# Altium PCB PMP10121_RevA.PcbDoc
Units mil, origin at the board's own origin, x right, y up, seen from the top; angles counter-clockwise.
Board outline 5650 x 1182.11 mil, 2 copper layers (Top Layer, Bottom Layer), stack 62 mil thick; 55 components, 32 nets, 129 pads, 74 vias.
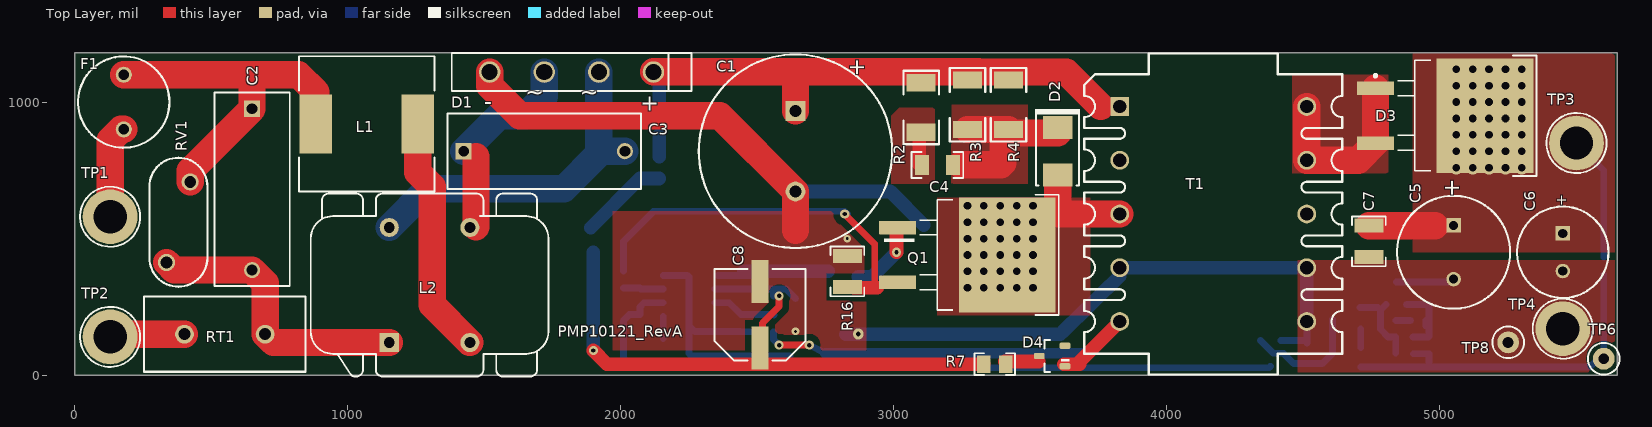
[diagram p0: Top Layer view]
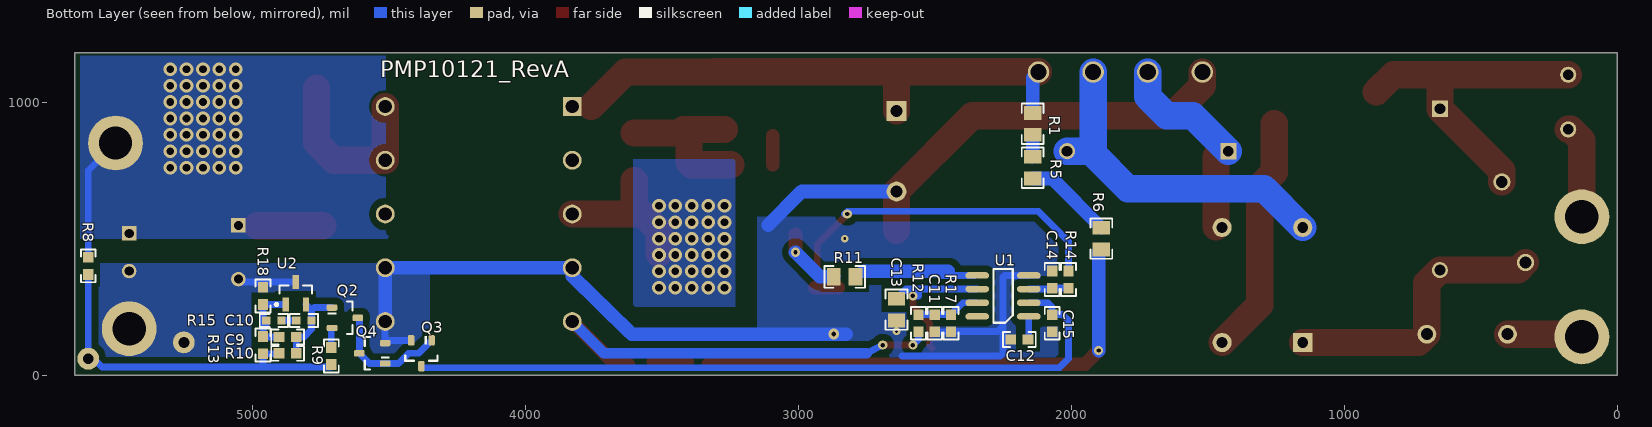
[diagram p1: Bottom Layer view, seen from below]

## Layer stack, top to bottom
Top Solder: solder mask 0.4, Solder Resist, Dk 3.5
Top Layer: signal copper 1.4
Dielectric1: core 59.2, FR-4, Dk 4.8
Bottom Layer: signal copper 1.4
Bottom Solder: solder mask 0.4, Solder Resist, Dk 3.5

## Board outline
0,0 5650,-1.01 5650,1180.1 0,1181.1

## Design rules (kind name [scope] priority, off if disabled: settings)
AcuteAngle [All] p1: minimum=4.50000000000000E+0001 checktracksonly=FALSE
AssemblyTestPointUsage [All] p1: valid=2
Clearance Clearance_Keepouts [((IsTrack Or IsArc) And Not InPoly) And IsFree and IsKeepOut vs ((IsTrack Or IsArc) And Not InPoly) And IsFree and IsKeepOut] p1: gap=0
Clearance Clearance_BoardEdge_MountingHoles [OnCopper and InComponentClass('Mounting Holes') vs IsKeepOut] p2: gap=40
Clearance Clearance_BoardEdge_Poly [OnCopper and InPoly vs IsKeepOut] p3: gap=25
Clearance Clearance_BoardEdge [OnCopper and Not InComponentClass('Logo') and not InComponentClass('FiducialMark') and not InRegion(1000,500,4000,800) and Not IsKeepout vs IsKeepOut] p4: gap=75
Clearance Clearance_Poly [InPolygon] p5: gap=25
Clearance [All] p6: gap=7.87
ComponentClearance ComponentClearance_MountingHoles_FiducialMarks [InComponentClass('Mounting Holes') vs InComponentClass('FiducialMark')] p1: gap=50 collisioncheckmode=3 verticalgap=10 showdistances=FALSE
ComponentClearance ComponentClearance_Shunt [InComponentClass('Header') vs InComponentClass('Shunt')] p2: gap=0 collisioncheckmode=3 verticalgap=0 showdistances=FALSE
ComponentClearance ComponentClearance_Logo [InComponentClass('Logo')] p3: gap=50 collisioncheckmode=3 verticalgap=10 showdistances=FALSE
ComponentClearance ComponentClearance_ScrewToNut [(HasFootprint('NY PMS 440 0025 PH')) vs (HasFootprint('Keystone_1902C'))] p4: gap=5 collisioncheckmode=3 verticalgap=10 showdistances=FALSE
ComponentClearance ComponentClearance_MountingHoles [InComponentClass('Mounting Holes')] p5: gap=250 collisioncheckmode=3 verticalgap=100000 showdistances=FALSE
ComponentClearance ComponentClearance_SmallPassives [HasFootprint('0201*') or HasFootprint('0402*') or HasFootprint('0508') or HasFootprint('0603*') or HasFootprint('0612') or HasFootprint('0805*') or HasFootprint('0815*') or HasFootprint('0830*') or HasFootprint('1206*') or HasFootprint('1210*') or HasFootprint('1808*') or HasFootprint('1812*') or HasFootprint('1825*') or HasFootprint('2010*') or HasFootprint('2220*') or HasFootprint('2225*') or HasFootprint('2512*') or HasFootprint('2728*') or HasFootprint('3518*') vs HasFootprint('0201*') or HasFootprint('0402*') or HasFootprint('0508') or HasFootprint('0603*') or HasFootprint('0612') or HasFootprint('0805*') or HasFootprint('0815*') or HasFootprint('0830*') or HasFootprint('1206*') or HasFootprint('1210*') or HasFootprint('1808*') or HasFootprint('1812*') or HasFootprint('1825*') or HasFootprint('2010*') or HasFootprint('2220*') or HasFootprint('2225*') or HasFootprint('2512*') or HasFootprint('2728*') or HasFootprint('3518*')] p6: gap=20 collisioncheckmode=3 verticalgap=10 showdistances=FALSE
ComponentClearance ComponentClearance_THtoSMT [IsThruComponent vs IsSMTComponent] p7: gap=10 collisioncheckmode=3 verticalgap=30 showdistances=FALSE
ComponentClearance ComponentClearance_THtoTH [IsThruComponent vs IsThruComponent] p8: gap=10 collisioncheckmode=3 verticalgap=30 showdistances=FALSE
ComponentClearance [All] p9: gap=40 collisioncheckmode=3 verticalgap=10 showdistances=FALSE
DiffPairsRouting [All] p1: maxlimit=100 minlimit=10 mostfreqgap=10 toplayer_minwidth=15 toplayer_maxwidth=15 toplayer_prefwidth=15 bottomlayer_minwidth=15 bottomlayer_maxwidth=15 bottomlayer_prefwidth=15 maxuncoupledlength=1000
FabricationTestPointUsage TestPointUsage [All] p1: valid=2 allowmultiple=FALSE
FabricationTestpoint Testpoint [All] p1: side=3 testpointundercomponent=TRUE minsize=40 maxsize=100 preferedsize=60 minholesize=0 maxholesize=40 preferedholesize=32 testpointgrid=1 allowsidetop=TRUE allowsidebottom=TRUE usegrid=TRUE gridtolerance=0.01
FanoutControl Fanout_LCC [IsLCC] p1: bgadir=Out bgaviamode=Centered fanoutstyle=Auto fanoutdirection=Alternating viagrid=1 // Fanout_LCC (Default Rule)
FanoutControl Fanout_BGA [IsBGA] p2: bgadir=Out bgaviamode=Centered fanoutstyle=Auto fanoutdirection=Alternating viagrid=1 // Fanout_BGA (Default Rule)
FanoutControl Fanout_Default [All] p4: bgadir=Out bgaviamode=Centered fanoutstyle=Auto fanoutdirection=Alternating viagrid=1 // Fanout_Default (Default Rule)
FanoutControl Fanout_Small [(CompPinCount < 5)] p5: bgadir=Out bgaviamode=Centered fanoutstyle=Auto fanoutdirection=OutThenIn viagrid=1 // Fanout_Small (Default Rule)
Height [All] p1: minheight=0 maxheight=1500 prefheight=500
HoleSize [All] p1: absolutevalues=TRUE maxlimit=251 minlimit=8 maxpercent=80.000 minpercent=20.000
MinimumAnnularRing MinimumAnnularRing_ThermalPadVias [IsVia and InAnyComponent] p1: minimumring=5.91
MinimumAnnularRing [All] p2: minimumring=9
MinimumSolderMaskSliver MinimumSolderMaskSliver_Logo [InComponentClass('Logo') vs InComponentClass('Logo')] p1: minsoldermaskwidth=0.7
MinimumSolderMaskSliver [All] p2: minsoldermaskwidth=3.94
PlaneConnect [All] p1: planeconnectstyle=Relief reliefexpansion=10 reliefentries=4 reliefconductorwidth=10 reliefairgap=10
PolygonConnect [All] p1: connectstyle=Direct reliefconductorwidth=10 reliefentries=4 polygonreliefangle="90 Angle" airgapwidth=10
RoutingVias ThermalPadVias [IsVia and InAnyComponent] p1: holewidth=7.87 width=19.68 viastyle="Through Hole" minholewidth=7.87 minwidth=19.68 maxholewidth=12.99 maxwidth=23.62
RoutingVias [All] p2: holewidth=16 width=34 viastyle="Through Hole" minholewidth=7.87 minwidth=26 maxholewidth=40 maxwidth=65
SilkToBoardRegionClearance [Not ((IsComment or IsDesignator) And (Hide <> 'False')) and not InRegion(1000,500,4000,800)] p1 off:
SilkToSilkClearance SilkToSilkClearance_Pb-FreeLogo [(HasFootprint('Pb-Free_Overlay_Medium') OR HasFootprint('Pb-Free_Overlay_Small')) vs (HasFootprint('Pb-Free_Overlay_Medium') OR HasFootprint('Pb-Free_Overlay_Small'))] p1: silktosilkclearance=0
SilkToSilkClearance [All] p2: silktosilkclearance=0
SilkToSolderMaskClearance "Silk to Solder Mask Opening" [All] p1: minsilkscreentomaskgap=0 clearancetoexposedcopper=FALSE
SolderMaskExpansion [All] p1: expansion=1.97
UnpouredPolygon [All] p1: allowunpoured=FALSE
Width [All] p1: maxlimit=100 minlimit=6 preferedwidth=10 checkconnectedcopper=TRUE
13 further rules are at their usual default settings.

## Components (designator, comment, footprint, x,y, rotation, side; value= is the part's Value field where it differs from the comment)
C1 "EEUED2W470" CAPPR7.5-18X31.5 2640,820 r270 top
C2 "B32922C3224K" B32922_12.5mm 650,680 r270 top
C3 "B32922C3224K" B32922_12.5mm 1720,820 r0 top
C4 "GRM31BR72J472KW01L" 1206 3160,770 r0 top
C5 "EKZN350ELL471MJ20S" KZN_1000x2000 5050,450 r270 top
C6 "EKZN350ELL221MH15D" KZN_800x1500 5450,450 r270 top
C7 "Used in BOM report" 1210 4740,490 r270 top
C8 "EEE-FC1V330P" SM_RADIAL_E 2510,221.5 r90 top
C9 "GRM188R71H103KA01D" 0603 4870,140 r180 bottom
C10 "Used in BOM report" 0603_HV 4810,200 r180 bottom
C11 "C0603C100J5GACTU" 0603 2500,190 r270 bottom
C12 "C1608X7R1H473K" 0603 2190,130 r0 bottom
C13 "GRM21BR71H104KA01L" 0805_HV 2640,240 r270 bottom
C14 "C0603C101J5GAC" 0603 2070,350 r90 bottom
C15 "C1608C0G1H102J" 0603 2070,190 r270 bottom
D1 "GBU8J-BP" GBU 1820,1110 r180 top
D2 "RS1MB-13-F" SMB 3600,820 r270 top
D3 "Used in BOM report" DDPAK#1 5010,950 r0 top
D4 "BAS21-7-F" SOT-23 3580,70 r180 top
F1 "37211600001" FUSE_372 180,1000 r270 top
L1 "MSS1210-334KE" IND_MSS1210 1070,920 r0 top
L2 "744823210" IND_WE-CMB_M 1300,330 r90 top
Q1 "STB11N65M5" DDPAK#2 3260,440 r0 top
Q2 "MMBT2907A" SOT-23 4660,210 r180 bottom
Q3 "MMBT3904" SOT-23 4380,80 r270 bottom
Q4 "MMBT3904" SOT-23 4560,80 r0 bottom
R1 "CRCW08052M00JNEA" 0805_HV 2141.46,920 r90 bottom
R2 "CRCW2010100RJNEF" 2010 3100,980 r90 top
R3 "CRCW2010100KJNEF" 2010 3270,990 r90 top
R4 "CRCW2010100KJNEF" 2010 3420,990 r90 top
R5 "CRCW08052M00JNEA" 0805_HV 2141.46,760 r90 bottom
R6 "CRCW08052M00JNEA" 0805_HV 1890,500 r90 bottom
R7 "CRCW080522R0JNEA" 0805_HV 3370,40 r0 top
R8 "CRCW060349R9FKEA" 0603 5600,400 r90 bottom
R9 "CRCW060320K0FKEA" 0603 4710,70 r270 bottom
R10 "CRCW060320K0FKEA" 0603 4870,80 r0 bottom
R11 "CRCW08050000Z0EA" 0805_HV 2830,360 r0 bottom
R12 "CRCW0603147KFKEA" 0603 2560,190 r270 bottom
R13 "CRCW060349K9FKEA" 0603 4960,110 r270 bottom
R14 "CRCW06031K43FKEA" 0603 2010,350 r90 bottom
R15 "Used in BOM report" 0603_HV 4920,200 r0 bottom
R16 "Used in BOM report" 1210 2830,380 r270 top
R17 "CRCW060334K8FKEA" 0603 2440,190 r90 bottom
R18 "CRCW06033K01FKEA" 0603 4960,290 r270 bottom
RT1 "B57237S109M" S237 550,150 r0 top
RV1 "S10K275E2" VAR_S10K275E2 380,560 r90 top
T1 "750315220" WURTH_750315220 4170,590 r0 top
TP1 "Suggest using a net name here" Keystone1503-2 130,580 r0 top
TP2 "Suggest using a net name here" Keystone1503-2 130,140 r0 top
TP3 "Suggest using a net name here" Keystone1503-2 5500,850 r0 top
TP4 "Suggest using a net name here" Keystone1503-2 5450,170 r0 top
TP6 "5000" Keystone5000 5600,60 r0 top
TP8 "5001" Keystone5001 5250,120 r0 top
U1 "UCC28600D" D0008A_N 2250,290 r0 bottom
U2 "LMV431AIMFX/NOPB" MF03A_N 4840,300 r90 bottom

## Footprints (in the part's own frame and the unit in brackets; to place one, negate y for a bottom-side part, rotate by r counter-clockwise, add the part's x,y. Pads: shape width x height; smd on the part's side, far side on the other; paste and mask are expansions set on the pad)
0603 [mm] "0603 from SM-752 data"
  rect 1x0.95 smd: 1(-0.8,0) 2(0.8,0)
  silkscreen extent -1.52,-0.69 1.52,0.69, body extent -0.87,-0.47 0.87,0.47, height 0.85
0603_HV [mil] "Ernesto recommended land pattern.  26 mil between pads."
  rect 30x30 smd: 1(-28,0) 2(28,0)
  silkscreen extent -52,-24 52,24, body extent -34,-19 34,19, height 33
0805_HV [mil] "0805 with 30mil clearance between pads"
  rect 50x63 smd: 1(-40,0) 2(40,0)
  silkscreen extent -74,-40 74,40, body extent -43,-29 43,29, height 43
1206 [mm] "1206 from SM-752 data"
  rect 1.3x1.85 smd: 1(-1.45,0) 2(1.45,0)
  silkscreen extent -2.4,-1.21 2.4,1.21, body extent -1.7,-0.9 1.7,0.9, height 1.35
1210 [mm] "1210 from SM-752 data"
  rect 1.3x2.7 smd: 1(-1.45,0) 2(1.45,0)
  silkscreen extent -2.32,-1.57 2.32,1.57, body extent -1.7,-1.35 1.7,1.35, height 1.35
2010 [mm] "Chip Capacitor, Body 5.08x2.54mm, IPC Medium Density"
  rect 1.6x2.7 smd: 1(-2.3,0) 2(2.3,0)
  silkscreen extent -3.42,-1.65 3.42,1.65, body extent -2.73,-1.45 2.73,1.45, height 1.66
B32922_12.5mm [mm] "Epcos film capacitors, 15mm spacing"
  rect 1.5x1.5 hole 1: 1(-7.5,0)
  round 1.5 hole 1: 2(7.5,0)
  silkscreen extent -9,-3.5 9,3.5, body extent -9,-3.5 9,3.5, height 12.5
CAPPR7.5-18X31.5 [mm] "Capacitor, Electrolytic, Radial; Body 18 x 31.5 mm (Dia.xH typ); Pin Spacing 7.5 mm (typ)"
  rect 1.85x1.85 hole 1.1: 1(-3.75,0)
  round 1.85 hole 1.1: 2(3.75,0)
  silkscreen extent -9,-9 9,9, body extent -9.01,-9.01 9.01,9.01, height 33.5
D0008A_N [mm] "SOIC, 8-Leads, Body 4.9x3.9mm, Pitch 1.27mm, IPC Medium Density"
  oval 2.2x0.6 smd: 1(-2.4,1.905) 2(-2.4,0.635) 3(-2.4,-0.635) 4(-2.4,-1.905) 5(2.4,-1.905) 6(2.4,-0.635) 7(2.4,0.635) 8(2.4,1.905)
  silkscreen extent -0.9,-2.5 0.9,2.5, body extent -3,-2.45 3,2.45, height 1.63
DDPAK#1 [mil] "D2-PAK, 3-Pads, Body 9.7x10.4mm (max), TO-263AB, using Vishay Silionix recommended pad sizes"
  rect 135x49.49 smd: 1(-246.06,100) 3(-246.06,-100)
  rect 355x420 smd paste-181.1: 4(155.51,0)
  silkscreen extent -251,-220 344,220, body extent -295,-202 324,202, height 180
DDPAK#2 [mil] "D2-PAK, 3-Pads, Body 9.7x10.4mm (max), TO-263AB, using Vishay Silionix recommended pad sizes"
  rrect8% 135x49.49 smd: 1(-246.06,100) 3(-246.06,-100)
  rrect1% 355x420 smd paste-181.1: 4(155.51,0)
  silkscreen extent -295,-220 344,220, body extent -295,-202 324,202, height 180
FUSE_372 [mm] "LITTELFUSE"
  round 1.5 hole 1: 1(-2.54,0) 2(2.54,0)
  silkscreen extent -4.25,-4.25 4.25,4.25, body extent -4.26,-4.26 4.26,4.26, height 8
GBU [mm] "Comchip / Diodes Inc diode bridge"
  round 2 hole 1.5: 1(-7.62,0) 2(-2.54,0) 3(2.54,0) 4(7.62,0)
  silkscreen extent -11.15,-1.78 11.15,1.78, body extent -11.15,-1.76 11.15,1.8, height 21.55
IND_MSS1210 [mm] "Coilcraft MSS1210 series"
  rect 3x5.5 smd: 1(-4.75,0) 2(4.75,0)
  silkscreen extent -6.3,-6.3 6.3,6.3, body extent -6.15,-6.15 6.15,6.15, height 10.2
IND_WE-CMB_M [mil] "Wurth"
  rect 70x70 hole 40: 1(-210.63,147.64)
  round 70 hole 40: 2(210.63,147.64) 3(210.63,-147.64) 4(-210.63,-147.64)
  silkscreen extent -335,-435 335,435, body extent -335,-394 335,394, height 1044
Keystone1503-2 [mm] "Double Turret"
  round 5.1 hole 3.1: 1(0,0)
  silkscreen extent -2.79,-2.79 2.79,2.79, body extent -2.4,-2.4 2.38,2.4, height 9.22
Keystone5000 [mil] "For Keystone 500x miniature loop terminals"
  round 80 hole 40: 1(0,0)
  silkscreen extent -58,-58 58,58, body extent -49,-49 49,49, height 182
Keystone5001 [mil] "For Keystone 500x miniature loop terminals"
  round 80 hole 40: 1(0,0)
  silkscreen extent -58,-58 58,58, body extent -49,-49 49,49, height 182
KZN_800x1500 [mm] "TH, 2-Leads, Dia 8mm, Pin Spacing 3.5mm"
  rect 1.35x1.35 hole 0.85: 1(-1.75,0)
  round 1.35 hole 0.85: 2(1.75,0)
  silkscreen extent -4.25,-4.25 4.25,4.25, body extent -4.22,-4.24 4.3,4.24, height 16.5
KZN_1000x2000 [mm] "TH, 2-Leads, Dia 10mm, Pin Spacing 5mm"
  rect 1.35x1.35 hole 0.85: 1(-2.5,0)
  round 1.35 hole 0.85: 2(2.5,0)
  silkscreen extent -5.25,-5.25 5.25,5.25, body extent -5.26,-5.26 5.26,5.26, height 21.5
MF03A_N [mm] "SOT23, 3-Leads, Body 2.9x1.3mm, Pitch 0.95mm, Lead Span 2.4mm, IPC Medium Density"
  rect 1.3x0.6 smd: 1(-1.05,0.95) 2(-1.05,-0.95) 3(1.05,0)
  silkscreen extent -1.17,-1.5 0.7,1.93, body extent -0.7,-1.5 0.7,1.5, height 1.12
S237 [mm] "EPCOS"
  round 1.75 hole 1.1: 1(-3.75,0) 2(3.75,0)
  silkscreen extent -7.5,-3.5 7.5,3.5, body extent -7.47,-3.5 7.47,3.5, height 21.99
SM_RADIAL_E [mm] "8 x 6.2mm:  Panasonic E"
  rect 4x1.6 smd: 1(-3.1,0) 2(3.1,0)
  silkscreen extent -4.25,-4.25 4.25,4.25, body extent -4.26,-4.26 4.26,4.26, height 6.5
SMB [mil] "Molded Diode, 2-Leads, Body 5.4x3.6mm, IPC Medium Density, based on OnSemi component dimensions"
  rect 85x107.99 smd: 1(-87.01,0) 2(87.01,0)
  silkscreen extent -155,-82 125,82, body extent -106,-71 106,71, height 91
SOT-23 [mm] "SOT23, 3-Leads, Body 2.9x1.3mm, Pitch 0.95mm, Lead Span 2.5mm, IPC Medium Density"
  rrect50% 1x0.6 smd: 1(-1.2,0.95) 2(-1.2,-0.95) 3(1.2,0)
  silkscreen extent -1.63,-1.5 0.7,1.5, body extent -1.16,-1.45 1.21,1.45, height 1
VAR_S10K275E2 [mm] "EPCOS"
  round 1.6 hole 1.1: 1(-3.75,1.1) 2(3.75,-1.1)
  silkscreen extent -6,-2.7 6,2.7, body extent -5.98,-2.7 5.98,2.7, height 14.99
WURTH_750315220 [mm] "TH, 10-Leads, Body 24x29.84mm, Pitch 5mm"
  rect 1.75x1.75 hole 1.25: 1(-8.7,10)
  round 1.75 hole 1.25: 2(-8.7,5) 3(-8.7,0) 4(-8.7,-5) 5(-8.7,-10) 6(8.7,-10) 7(8.7,-5) 8(8.7,0) 9(8.7,5) 10(8.7,10)
  silkscreen extent -12,-14.92 12,14.92, body extent -12,-14.92 12,14.92, height 33

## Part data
C1: "CAP, AL, 47 µF, 450 V, +/- 20%, 0.609529 ohm, TH"
C2 C3: "CAP, Film, 0.22 µF, 630 V, +/- 10%, TH"
C4: "CAP, CERM, 4700 pF, 630 V, +/- 10%, X7R, 1206"
C5: "CAP, AL, 470 µF, 35 V, +/- 20%, 0.028 ohm, TH"
C6: "CAP, AL, 220 µF, 35 V, +/- 20%, 0.059 ohm, TH"
C7 C10: library part Capacitor, "CAP, CERM, xxxF, xxV, [TempCo], xx%, [PackageReference]"
C8: "CAP, AL, 33 µF, 35 V, +/- 20%, 0.4 ohm, SMD"
C9: "CAP, CERM, 0.01 µF, 50 V, +/- 10%, X7R, 0603"
C11: "CAP, CERM, 10 pF, 50 V, +/- 5%, C0G/NP0, 0603"
C12: "CAP, CERM, 0.047 µF, 50 V, +/- 10%, X7R, 0603"
C13: "CAP, CERM, 0.1 µF, 50 V, +/- 10%, X7R, 0805"
C14: "CAP, CERM, 100 pF, 50 V, +/- 5%, C0G/NP0, 0603"
C15: "CAP, CERM, 1000 pF, 50 V, +/- 5%, C0G/NP0, 0603"
D1: "Diode, Switching-Bridge, 420 V, 8 A, TH"
D2: "Diode, P-N, 1000 V, 1 A, SMB"
D3: library part Diode_Schottky_A3C4, "Diode, Schottky, xxV, xxA, [PackageReference]"
D4: "Diode, Switching, 200 V, 0.2 A, SOT-23"
F1: "Fuse, 1.6 A, 250 V, TH"
L1: "Inductor, Shielded, Ferrite, 330 µH, 1.7 A, 0.317 ohm, SMD"
L2: "Coupled inductor, 10 mH, 2 A, 0.125 ohm, +/- 30%, TH"
Q1: "MOSFET, N-CH, 710 V, 9 A, DDPAK"
Q2: library part "MMBT2907A, Fairchild Semiconductor", "Transistor, PNP, 60 V, 0.8 A, SOT-23"
Q3 Q4: library part "MMBT3904, Fairchild Semiconductor", "Transistor, NPN, 40 V, 0.2 A, SOT-23"
R1 R5 R6: "RES, 2.0 M, 5%, 0.125 W, 0805"
R2: "RES, 100, 5%, 0.75 W, 2010"
R3 R4: "RES, 100 k, 5%, 0.75 W, 2010"
R7: "RES, 22, 5%, 0.125 W, 0805"
R8: "RES, 49.9, 1%, 0.1 W, 0603"
R9 R10: "RES, 20.0 k, 1%, 0.1 W, 0603"
R11: "RES, 0, 5%, 0.125 W, 0805"
R12: "RES, 147 k, 1%, 0.1 W, 0603"
R13: "RES, 49.9 k, 1%, 0.1 W, 0603"
R14: "RES, 1.43 k, 1%, 0.1 W, 0603"
R15 R16: library part Resistor, "RES, xxx ohm, x%, xW, [PackageReference]"
R17: "RES, 34.8 k, 1%, 0.1 W, 0603"
R18: "RES, 3.01 k, 1%, 0.1 W, 0603"
RT1: "Thermistor NTC, 1 ohm, 20%, 15x7mm"
RV1: "Varistor 275V RMS 10MM Radial, TH"
T1: "Transformer, 400 uH, TH"
TP1 TP2 TP3 TP4: library part 1503-2, "Terminal, Turret, TH, Double"
TP6: "Test Point, Miniature, Red, TH"
TP8: "Test Point, Miniature, Black, TH"
U1: "Quasi-Resonant Flyback Green-Mode Controller with Current Control, 99 % Duty Cycle, -40 to +105 degC, 8-pin SOIC (D), Green (RoHS & no Sb/Br)"
U2: "Low-Voltage (1.24V) Adjustable Precision Shunt Regulators, 3-pin SOT-23, Pb-Free"

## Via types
v1: diameter 50, hole 28, Top Layer to Bottom Layer, 65 vias
v2: diameter 34, hole 16, Top Layer to Bottom Layer, 6 vias
v3: diameter 28, hole 10, Top Layer to Bottom Layer, 2 vias
v4: diameter 40, hole 18, Top Layer to Bottom Layer, 1 vias

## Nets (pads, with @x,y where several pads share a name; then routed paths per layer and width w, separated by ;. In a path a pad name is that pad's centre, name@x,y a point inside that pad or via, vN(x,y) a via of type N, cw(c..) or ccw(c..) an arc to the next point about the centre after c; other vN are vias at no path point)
GND: C1.2 C5.2 C6.2 C7.2 C8.2 C11.2 C12.2 C13.2 C14.2 C15.2 D1.4 Q3.2 Q4.2 R16.1 R17.1 R18.1 T1.4 T1.6 T1.7 TP4.1 TP8.1 U1.4 U2.3 | length 5356.7
  Top Layer w100: D1.4 1520,1060 1630,950 2362.36,950 C1.2 ; 2640,530 C1.2@2640,660
  Bottom Layer w25: U1.4 2245,365 2250,360 2250,180 ; C11.2 R17.1 2438.5,160 2270,160 2250,180 ; 2620,70 2260,70 2250,80 2250,180 ; Q3.2 Q4.2@4502.91,127.24 ; Q4.2 T1.6@4512.76,196.06 ; U2.3 5039.76,341.34 C5.2
  Bottom Layer w50: C1.2 2987.64,672.36 3110,550 ; 2825.04,150 3610,150 ; 3620,160 3827.48,362.52 T1.4 T1.7 T1.6
  other v3: 2640,160 2830,500
  other v4: 2870,150
NetC1_1: C1.1 D1.1 R1.2 R2.2 R3.2 R4.2 T1.1 | length 1982.4
  Top Layer w100: D1.1 2120,1110.55 3200.39,1110.55 ; C1.1@2640,967.09 2640,1100 ; 3200.94,1110 3200.39,1110.55 ; R3.2@3310.39,1110.55 3200.39,1110.55 ; R3.2@3310.94,1110 3631.18,1110 3757.48,983.7
  Bottom Layer w50: D1.1 2141.46,1088.54 R1.2
NetC2_1: C2.1 F1.1 L1.1 RV1.2 | length 1215.3
  Top Layer w100: F1.1 650,1100 ; RV1.2 423.31,748.58 C2.1 650,1100 ; 882.99,1037.01 820,1100 650,1100
NetC2_2: C2.2 L2.1 RT1.2 RV1.1 | length 1046.6
  Top Layer w100: RV1.1 364.33,384.72 C2.2 697.64,337.09 RT1.2 728.27,119.37 L2.1
NetC3_1: C3.1 D1.3 L2.3 | length 724.6
  Top Layer w100: L2.3@1470,543.54 1470,800
  Bottom Layer w100: C3.1 1554.72,950 1650,950 1720,1020 D1.3
NetC3_2: C3.2 D1.2 L2.2 | length 1264.5
  Bottom Layer w100: L2.2 1293.94,682.2 1792.2,682.2 1920,810 D1.2 ; 1930,820 C3.2
NetC4_1: C4.1 R2.1 | length 106.5
  Top Layer w50: C4.1@3093.07,770 R2.1@3093.07,876.54
NetC4_2: C4.2 D2.1 R3.1 R4.1 | length 594.2
  Top Layer w100: 3247.09,770 3392.99,770 ; R3.1 R4.1 3400,879.45 3400,777.01 ; R4.1@3432.44,887.01 D2.1@3600,887.01
NetC5_1: C5.1 C6.1 C7.1 D3.4 R8.2 TP3.1 | length 701.7
  Top Layer w100: C7.1 4981.81,547.09
  Bottom Layer w25: TP3.1 5600,750 R8.2
  other v1: 5060,760 5120,760 5180,760 5240,760 5300,760 5060,820 5120,820 5180,820 5240,820 5300,820 5060,880 5120,880 5180,880 5240,880 5300,880 5060,940 5120,940 5180,940 5240,940 5300,940 5060,1000 5120,1000 5180,1000 5240,1000 5300,1000 5060,1060 5120,1060 5180,1060 5240,1060 5300,1060 5060,1120 5120,1120 5180,1120 5240,1120 5300,1120
NetC9_1: C9.1 R13.1 R15.2 R18.2 U2.1 | length 291.4
  Bottom Layer w25: U2.1 R18.2@4959.84,258.66 ; C9.1 R13.1@4958.5,140 ; R15.2 4948,181.98 4960,169.98 ; R13.1 4960,169.98 ; R18.2 4960,169.98
NetC9_2: C9.2 C10.2 Q2.1 R10.1 U2.2 | length 292.7
  Bottom Layer w25: Q2.1 4772.66,247.4 ; U2.2 4782,238.06 C10.2 4782,168.02 4810.02,140 C9.2 R10.1
NetC10_1: C10.1 R15.1 | length 54
  Bottom Layer w25: C10.1 R15.1
NetC11_1: C11.1 R12.1 R17.2 U1.7 | length 235.6
  Bottom Layer w25: U1.7 2396.5,265 R17.2 C11.1 R12.1 R12.1@2561.5,220
NetC12_1: C12.1 U1.1 | length 82
  Bottom Layer w25: C12.1@2155.51,132.99 U1.1
NetC14_1: C14.1 R14.1 U1.3 | length 147
  Bottom Layer w25: R14.1 C14.1 2073.5,315 U1.3
NetC15_1: C15.1 Q3.3 U1.2 | length 2711
  Bottom Layer w25: U1.2 2085.02,265 2070,249.98 C15.1 2031.5,221.5 2010,200 2010,60 2042.87,27.13 Q3.3@4374.37,27.13 ; Q3.3@4377.24,30 Q3.3
NetD2_2: D2.2 Q1.4 T1.3 | length 520.6
  Top Layer w100: Q1.4@3510,444.49 3510,530.47 3569.53,590 T1.3 ; 3600,620.47 D2.2@3600,712.99
  other v1: 3270,320 3330,320 3390,320 3450,320 3510,320 3270,380 3330,380 3390,380 3450,380 3510,380 3270,440 3330,440 3390,440 3450,440 3510,440 3270,500 3330,500 3390,500 3450,500 3510,500 3270,560 3330,560 3390,560 3450,560 3510,560 3270,620 3330,620 3390,620 3450,620 3510,620
NetD3_1: D3.1 D3.3 T1.9 T1.10 | length 674.4
  Top Layer w100: T1.10 T1.9 4700.79,786.85 D3.3 D3.1
NetD4_1: D4.1 R12.2 T1.5 | length 1619.3
  Top Layer w25: v2(2580,110) v2(2690,110)
  Top Layer w50: D4.1@3623.46,40 3680,40 ; 3683.78,52.6 T1.5
  Bottom Layer w25: 2559.98,130.02 v2(2580,110) ; 2560,130.04 R12.2 ; v2(2690,110) 2750,80
  Bottom Layer w40: 2750,80 3711.18,80 T1.5
NetD4_3: D4.3 R7.2 | length 122.8
  Top Layer w50: R7.2@3407.24,50 3530,50
NetF1_2: F1.2 TP1.1 | length 346.6
  Top Layer w100: TP1.1 130,860 170,900 F1.2
NetL1_2: L1.2 L2.4 | length 879.6
  Top Layer w100: L1.2 1257.01,742.99 1310,690 1310,257.01 L2.4
NetQ1_1: Q1.1 R11.2 | length 243.3
  Top Layer w50: v2(3010,450) Q1.1@3010,516.06
  Bottom Layer w50: R11.2 2920,360 v2(3010,450)
NetQ1_3: Q1.3 R14.2 R16.2 | length 1380.9
  Top Layer w25: v2(2820,590) 2930,480 2930,320
  Top Layer w50: R16.2@2852.91,320 2940,320
  Bottom Layer w25: R14.2 2010,490 2120,600 2820,600 v2@2830,590
NetQ2_2: Q2.2 R9.1 | length 68.3
  Bottom Layer w25: R9.1 Q2.2@4710,169.84
NetQ2_3: Q2.3 Q3.1 Q4.1 Q4.3 | length 439.7
  Bottom Layer w25: Q3.1 4389.84,80 4427.07,80 4464.47,42.6 Q4.1 4569.84,42.6 Q4.3 Q2.3@4607.24,204.49
NetR1_1: R1.1 R5.2 | length 80
  Bottom Layer w50: R5.2 R1.1
NetR5_1: R5.1 R6.2 | length 326
  Bottom Layer w50: R6.2 2070,720 R5.1
NetR8_1: R8.1 R9.2 R10.2 R13.2 TP6.1 | length 1304.7
  Bottom Layer w25: R9.2@4710,30 4960,30 ; R10.2@4902.99,78.5 R13.2 4960,30 ; R8.1 5600,80 5550,30 4960,30
NetR11_1: R11.1 U1.5 | length 430.5
  Bottom Layer w25: U1.5@2354.49,365 2475,365
  Bottom Layer w50: 2450,380 2760,380
NetRT1_1: RT1.1 TP2.1 | length 262.4
  Top Layer w100: TP2.1@140,150 RT1.1
VDD: C8.1 C13.1 R6.1 R7.1 U1.6 | length 2375.3
  Top Layer w25: C8.1 2518.7,108.15 2518.7,190 2580,251.3 v2(2580,290)
  Top Layer w50: v2(1900,90) 1950,40 R7.1
  Bottom Layer w25: U1.6 2560,315 ; v2@2570,290 2560,290 2560,315 ; C13.1 2605,315 2560,315
  Bottom Layer w50: v2(1900,90) R6.1@1900,450
pads on no net: D4.2 T1.2 T1.8 U1.8

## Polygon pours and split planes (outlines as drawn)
NetD3_1 on Top Layer "Top Layer-No Net 6" (solid, remove dead copper, pour order 36): 4460,1100 4810,1100 4810,733.46 4803.46,740 4460,740
NetD2_2 on Top Layer "Top Layer-No Net 5" (solid, remove dead copper, pour order 30): 3160,650 3720,650 3720,220 3160,220
GND on Top Layer "Top Layer-No Net 4" (solid, remove dead copper, pour order 16): 1970,600 2900,600 2900,10 1970,10
GND on Top Layer "Top Layer-No Net 3" (solid, remove dead copper, pour order 12): 4480,420 5640,420 5640,10 4480,10
NetC5_1 on Top Layer "Top Layer-No Net" (solid, remove dead copper, pour order 10): 4900,1180 4900,450 5640,450 5640,1170 5630,1180
NetC4_1 on Top Layer "Top Layer-No Net 2" (solid, remove dead copper, pour order 8): 3150,700 3150,980 3020,980 2990,950 2990,700
NetC4_2 on Top Layer "Top Layer-No Net 1" (solid, remove dead copper, pour order 6): 3212.93,990 3490,990 3490,700 3220,700 3210,690
NetC5_1 on Bottom Layer "Bottom Layer-No Net 3" (solid, remove dead copper, pour order 34): 5630,500 4490,500 4510,520 4510,1170 5630,1170
GND on Bottom Layer "Bottom Layer-No Net 2" (solid, remove dead copper, pour order 32): 4350,20 4350,410 5640,410 5650,420 5630,400 5630,20
NetD2_2 on Bottom Layer "Bottom Layer-No Net 1" (solid, remove dead copper, pour order 28): 3230,250 3604,250 3604,790 3230,790
GND on Bottom Layer "Bottom Layer-No Net" (solid, remove dead copper, pour order 18): 1810,580 3150,580 3150,10 1810,10

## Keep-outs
Keep-Out Layer:
  text ".Layer_Name" at 577,-858.49 h60

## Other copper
Top Layer:
  text ".Layer_Name" at 577,-858.49 h60
Bottom Layer:
  text ".Layer_Name" at 577,-858.49 h60

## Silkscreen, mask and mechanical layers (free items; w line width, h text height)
Top Overlay:
  text "PMP10121_RevA" at 1770,140 h40
  text ".Layer_Name" at 577,-858.49 h60
Bottom Overlay:
  text "PMP10121_RevA" at 4530,1090 h60
  text ".Layer_Name" at 577,-858.49 h60
Top Paste:
  text ".Layer_Name" at 577,-858.49 h60
Bottom Paste:
  text ".Layer_Name" at 577,-858.49 h60
Top Solder:
  text ".Layer_Name" at 577,-858.49 h60
  text ".Layer_Name" at 577,-858.49 h60
Bottom Solder:
  text ".Layer_Name" at 577,-858.49 h60
Drill Guide:
  text ".Layer_Name" at 577,-858.49 h60
M1 Board Outline:
  the board outline again, w10
  text ".Layer_Name" at 577,-858.49 h60
M2 Board Dimensions:
  rectangle: 125,-400 500,-275
  rectangle: 0,-275 125,-150
  lines w7: 0,-275 1000,-275 ; 125,-400 125,-150 ; 250,-400 250,-150 ; 500,-400 500,-150 ; 750,-400 750,-150 ; 0,-400 0,-150 1000,-150 1000,-400 0,-400
  text ".Layer_Name" at 577,-858.49 h60
M3 3D STEP Top:
  text ".Layer_Name" at 577,-858.49 h60
M4 3D STEP Bottom:
  text ".Layer_Name" at 577,-858.49 h60
M5 Assembly Top:
  lines w10: -292,-930.17 6308,-930.17 ; -292,-726.83 6310,-726.83 ; -292,-523.5 -292,-1133.5 3713,-1133.5 6310,-1133.5 6310,-523.5 -291.5,-523.5 -291.5,-1133.5 1284,-1133.5 ; 2173,-1133.5 2173,-523.5 ; 3440,-726.83 3440,-523.5 ; 4280,-726.83 4280,-523.5 ; 4902,-1140 4902,-937.17
  text "PCB VIEWED FROM TOP SIDE" at -228.5,-655.67 h60
  text "BOARD #:" at 2248,-655.67 h60
  text ".PRJ_Number" at 2793.5,-655.67 h60
  text "REV:" at 3638,-655.67 h60
  text ".PCB_Rev" at 3929.5,-655.67 h60
  text "SVN REV:" at 4476,-655.67 h60
  text ".VersionControl_RevNumber" at 4982,-655.67 h60
  text "PLOT NAME =" at -228.5,-1064.34 h60
  text ".plot_File_Name" at 577,-1064.34 h60
  text "GENERATED    :" at 2250,-1064.34 h60
  text ".Print_Date" at 3119.5,-1064.34 h60
  text ".Print_Time" at 3848.5,-1064.34 h60
  text "TEXAS INSTRUMENTS" at 5113,-1064.34 h60
M6 Assembly Bottom:
  lines w10: -292.5,-727.33 6309.5,-727.33 ; -290.5,-930.67 6309.5,-930.67 ; 1115.5,-1140.5 1115.5,-937.67 ; 1737.5,-727.33 1737.5,-524 ; 2577.5,-727.33 2577.5,-524 ; 3844.5,-1134 3844.5,-524 ; 4733.5,-1134 6309,-1134 6309,-524 -292.5,-524 -292.5,-1134 2304.5,-1134 6309.5,-1134 6309.5,-524
  text ".VersionControl_RevNumber" at 1035.5,-656.17 h60
  text "SVN REV:" at 1541.5,-656.17 h60
  text ".PCB_Rev" at 2088,-656.17 h60
  text "REV:" at 2379.5,-656.17 h60
  text ".PRJ_Number" at 3224,-656.17 h60
  text "BOARD #:" at 3769.5,-656.17 h60
  text "PCB VIEWED FROM BOTTOM SIDE" at 6246,-656.17 h60
  text "TEXAS INSTRUMENTS" at 904.5,-1064.84 h60
  text ".Print_Time" at 2169,-1064.84 h60
  text ".Print_Date" at 2898,-1064.84 h60
  text "GENERATED    :" at 3767.5,-1064.84 h60
  text ".plot_File_Name" at 5440.5,-1064.84 h60
  text "PLOT NAME =" at 6246,-1064.84 h60
M9 Title Sheet:
  drawing of 57 lines, arcs and shapes, not listed
  text "1" at 739.84,8036.5 h70
  text "2" at 3235.5,8036.5 h70
  text "3" at 5724.84,8036.5 h70
  text "4" at 8231.51,8036.5 h70
  text "5" at 10730.5,8036.5 h70
  text "6" at 13235.5,8036.5 h70
  text "A" at -416.5,6893.5 h70
  text "A" at 14383.5,6893.5 h70
  text "B" at -416.5,4513.5 h70
  text "B" at 14383.5,4513.5 h70
  text "C" at -416.5,2138.5 h70
  text "C" at 14383.5,2138.5 h70
  text "PROJECT TITLE:" at 11343.5,277.5 h45
  text ".PRJ_Title" at 11393.5,144.17 h70
  text "DESIGNED FOR:" at 11343.5,-23.5 h45
  text ".PRJ_Customer" at 11393.5,-163.5 h70
  text "D" at -416.5,-231.5 h70
  text "D" at 14383.5,-231.5 h70
  text "FILE NAME:" at 11343.5,-323.5 h45
  text ".PCB_File_Name_No_Path" at 11393.5,-443.5 h70
  text "Texas Instruments (TI) and/or its licensors do not warrant the accuracy or completeness of this specification" at 6374,-605.34 h45
  text "ENGINEER:" at 11343.5,-613.5 h45
  text "LAYOUT BY:" at 12848.5,-613.5 h45
  text "or any information contained therein. TI and/or its licensors do not warrant that this design will meet" at 6329.01,-718 h45
  text ".PRJ_Engineer" at 11393.5,-768.49 h70
  text ".PCB_Layout" at 12899,-768.49 h70
  text "the specifications, will be suitable for your application or fit for any particular purpose, or will operate in" at 6329.01,-830.67 h45
  text ".Layer_Name" at 577,-858.49 h60
  text "ALTIUM DESIGNER VERSION:" at 12848.5,-923.5 h45
  text "an implementation. TI and/or its licensors do not warrant that the design is production worthy. You should" at 6329.01,-943.33 h45
  text "completely validate and test your design implementation to confirm the system functionality for your application." at 6374,-1056 h45
  text ".print_Scale" at 11393.5,-1056.83 h70
  text ".Application_BuildNumber" at 12899,-1056.83 h70
  text "1" at 739.84,-1263.5 h70
  text "2" at 3235.5,-1263.5 h70
  text "3" at 5724.84,-1263.5 h70
  text "4" at 8231.51,-1263.5 h70
  text "5" at 10730.5,-1263.5 h70
  text "6" at 13235.5,-1263.5 h70
M10 Fab Notes:
  drawing of 185 lines, arcs and shapes, not listed
  text "DESIGN INFORMATION" at 12381.02,5910 h60
  text "MIN. TRACK WIDTH:" at 11736.46,5730 h60
  text "8" at 12832.7,5730 h60
  text "MIL" at 12987.46,5730 h60
  text "MIN. CLEARANCE:" at 11736.46,5598 h60
  text "0.2" at 12772.7,5598 h60
  text "mm" at 12987.46,5598 h60
  text "MIN. VIA PAD SIZE:" at 11736.46,5466 h60
  text "24" at 12802.71,5466 h60
  text "MIL" at 12987.46,5466 h60
  text "0.05mm (2MIL)" at 12431.46,5324.29 h60
  text "MINIMUM ANNULAR RING" at 11407.23,5320 h60
  text "EXTERNAL" at 13139.46,5320 h60
  text "PER" at 11607.23,5202 h60
  text "IPC-D-275 CLASS 2 LEVEL C" at 11827.23,5202 h60
  text "MIL, HOLES" at 13315.46,5089.71 h60
  text "+/-" at 12923,5089 h60
  text "+/-" at 13777,5089 h60
  text "REGISTRATION TOLERANCES:" at 11407.23,5084 h60
  text "METAL" at 12607,5084 h60
  text "5" at 13183.2,5084 h60
  text "3" at 14016.2,5084 h60
  text "MIL" at 14132.46,5084 h60
  text "MATERIAL:" at 11332.46,4874.54 h60
  text "FR-4 High Tg" at 12318.9,4734.21 h60
  text "FR-408" at 11753.46,4725.64 h60
  text "X" at 12165.46,4725.64 h60
  text "OTHER" at 13241.46,4725.64 h60
  text "62 MIL (1.6mm) +/-10%" at 12073.56,4562.92 h60
  text "THICKNESS:" at 11407.23,4558.64 h60
  text "X" at 11945.4,4558.64 h60
  text "OTHER" at 13358.46,4558.64 h60
  text "TOLERANCE:" at 11407.23,4400.64 h60
  text "X" at 12246.53,4400.64 h60
  text "ANSI IPC-6012 TYPE 3 CLASS 2" at 12433.48,4400.64 h60
  text "OTHER +/-" at 12433.46,4244.64 h60
  text "BOW & TWIST:" at 11407.23,4087.64 h60
  text "X" at 12246.53,4087.64 h60
  text "ANSI IPC-6012 TYPE 3 CLASS 2" at 12433.48,4087.64 h60
  text "OTHER +/-" at 12433.46,3929.13 h60
  text "DRILLING:" at 11332.46,3790.64 h60
  text "REFERENCE:" at 11407.23,3673.64 h60
  text "X" at 12055.46,3673.64 h60
  text "AS SHOWN" at 12242.46,3673.64 h60
  text "X" at 12956.46,3673.64 h60
  text "NC_DRILL FILES" at 13093.46,3673.64 h60
  text "PTH MIN COPPER THICKNESS:" at 11407.23,3515.64 h60
  text "X" at 12757.46,3515.64 h60
  text "1MIL" at 12894.46,3515.64 h60
  text "OTHER" at 13391.46,3515.64 h60
  text "BOARD FINISH:" at 11332.46,3356.64 h60
  text "SILKSCREEN:" at 11487.68,3238.64 h60
  text "X" at 12436.46,3238.64 h60
  text "TOP" at 12562.46,3238.64 h60
  text "X" at 12946.46,3238.64 h60
  text "BOTTOM" at 13073.46,3238.64 h60
  text "SILKSCREEN COLOR:" at 11487.68,3071.64 h60
  text "X" at 12435.42,3071.64 h60
  text "WHITE" at 12562.46,3071.64 h60
  text "OTHER" at 13073.46,3071.64 h60
  text "SOLDER RESIST COLOR:" at 11487.68,2901.64 h60
  text "X" at 12055.42,2742.44 h60
  text "GREEN" at 12182.46,2742.44 h60
  text "BLUE" at 12773.46,2742.44 h60
  text "OTHER" at 13311.46,2742.44 h60
  text "IMMERSION GOLD (ENIG)" at 12393.46,2553.92 h60
  text "ENEPIG" at 13731,2550.64 h60
  text "SURFACE FINISH:" at 11332.46,2549.64 h60
  text "X" at 12206.51,2549.64 h60
  text "IMM. TIN/SILVER OR EQUIV" at 11662,2392.64 h60
  text "OTHER" at 13093.46,2392.64 h60
  text "ARRAY/PANEL:" at 11332.46,2213.64 h60
  text "CUT AND TRIM PER MECH LAYER 1" at 12393.46,2209.35 h60
  text "N.C. ROUTE" at 12393.46,2057.64 h60
  text "X" at 13072.46,2057.64 h60
  text "V. SCORE" at 13259.46,2057.64 h60
  text "CERTIFICATION:" at 11332.46,1920.64 h60
  text "MATERIALS AND WORKMANSHIP FOR ALL PCBS" at 12057.46,1920.64 h60
  text "TO MEET OR EXCEED THE REQUIREMENTS OF:" at 12057.46,1822.64 h60
  text "X" at 11683.96,1686.13 h60
  text "ANSI IPC-A-600F CLASS ->" at 11822.96,1686.13 h60
  text "X" at 13462.02,1686.13 h60
  text "2" at 13580.96,1686.14 h60
  text "1" at 13265.96,1684.64 h60
  text "3" at 13934.96,1684.64 h60
  text "X" at 11686.02,1526.64 h60
  text "UL 94V-0" at 11822.96,1526.64 h60
  text "X" at 12498.02,1526.64 h60
  text "RoHS" at 12634.96,1526.64 h60
  text "OTHER" at 13279.36,1526.64 h60
  text "PER ORDER" at 13676.42,1526.64 h60
  text "ADDITIONAL REQUIREMENTS:" at 11332.46,1385.64 h60
  text "MICROSECTION:" at 11407.23,1270.64 h60
  text "YES" at 12312.96,1270.64 h60
  text "REQUIRED" at 13174.46,1114.49 h60
  text "BARE BOARD ELEC. TEST:" at 11407.23,1111.64 h60
  text "NONE" at 12712.96,1111.64 h60
  text "X" at 13047.46,1111.64 h60
  text "PER ORDER" at 13766.46,1111.64 h60
  text "MANUFACTURER'S UL:" at 11407.23,954.64 h60
  text "RAIL" at 12572.96,950.35 h60
  text "METAL" at 13064.77,950.35 h60
  text "X" at 13440,950 h60
  text "SILK" at 13576.46,950.35 h60
  text ".Layer_Name" at 577,-858.49 h60
M11 Gerber Information:
  lines w10: -292,-930.17 6308,-930.17 ; -292,-726.83 6310,-726.83 ; -292,-523.5 -292,-1133.5 3713,-1133.5 6310,-1133.5 6310,-523.5 -291.5,-523.5 -291.5,-1133.5 1284,-1133.5 ; 2173,-1133.5 2173,-523.5 ; 3440,-726.83 3440,-523.5 ; 4280,-726.83 4280,-523.5 ; 4902,-1140 4902,-937.17
  text "ALL ARTWORK VIEWED FROM TOP SIDE" at -228.5,-655.67 h60
  text "BOARD #:" at 2248,-655.67 h60
  text ".PRJ_Number" at 2793.5,-655.67 h60
  text "REV:" at 3638,-655.67 h60
  text ".PCB_Rev" at 3929.5,-655.67 h60
  text "SVN REV:" at 4476,-655.67 h60
  text ".VersionControl_RevNumber" at 4982,-655.67 h60
  text "LAYER NAME =" at -228.5,-858.49 h60
  text "PLOT NAME =" at -228.5,-1064.34 h60
  text ".plot_File_Name" at 577,-1064.34 h60
  text "GENERATED    :" at 2250,-1064.34 h60
  text ".Print_Date" at 3119.5,-1064.34 h60
  text ".Print_Time" at 3848.5,-1064.34 h60
  text "TEXAS INSTRUMENTS" at 5113,-1064.34 h60
M12 Stackup:
  drawing of 191 lines, arcs and shapes, not listed
  text "Layer" at 9790.34,7830 h60
  text "Name" at 10200.26,7830 h60
  text "Material" at 11130,7830 h60
  text "Thickness" at 11989.77,7830 h60
  text "Constant" at 12639.6,7830 h60
  text "Board Layer Stack" at 13209.46,7830 h60
  text "1" at 9790.34,7710 h60
  text "Top Overlay" at 10200.26,7710 h60
  text "2" at 9790.34,7590 h60
  text "Top Solder" at 10200.26,7590 h60
  text "Solder Resist" at 11130,7590 h60
  text "0.40mil" at 11989.77,7590 h60
  text "3.5" at 12639.6,7590 h60
  text "3" at 9790.34,7470 h60
  text "Top Layer" at 10200.26,7470 h60
  text "Copper" at 11130,7470 h60
  text "1.40mil" at 11989.77,7470 h60
  text "4" at 9790.34,7350 h60
  text "Dielectric1" at 10200.26,7350 h60
  text "FR-4" at 11130,7350 h60
  text "59.20mil" at 11989.77,7350 h60
  text "4.8" at 12639.6,7350 h60
  text "5" at 9790.34,7230 h60
  text "Bottom Layer" at 10200.26,7230 h60
  text "Copper" at 11130,7230 h60
  text "1.40mil" at 11989.77,7230 h60
  text "6" at 9790.34,7110 h60
  text "Bottom Solder" at 10200.26,7110 h60
  text "Solder Resist" at 11130,7110 h60
  text "0.40mil" at 11989.77,7110 h60
  text "3.5" at 12639.6,7110 h60
  text "7" at 9790.34,6990 h60
  text "Bottom Overlay" at 10200.26,6990 h60
  text ".Layer_Name" at 577,-858.49 h60
M13 Component Bodies Top:
  text ".Layer_Name" at 577,-858.49 h60
M14 Component Bodies Bottom:
  text ".Layer_Name" at 577,-858.49 h60
M15 Courtyards Top:
  text ".Layer_Name" at 577,-858.49 h60
M16 Courtyards Bottom:
  text ".Layer_Name" at 577,-858.49 h60
Drill Drawing:
  text ".Layer_Name" at 577,-858.49 h60

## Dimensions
0,0 to 5650,-1.01 on M2 Board Dimensions
0,0 to 0,1181.1 on M2 Board Dimensions
0,-400 to 1000,-400 on M2 Board Dimensions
